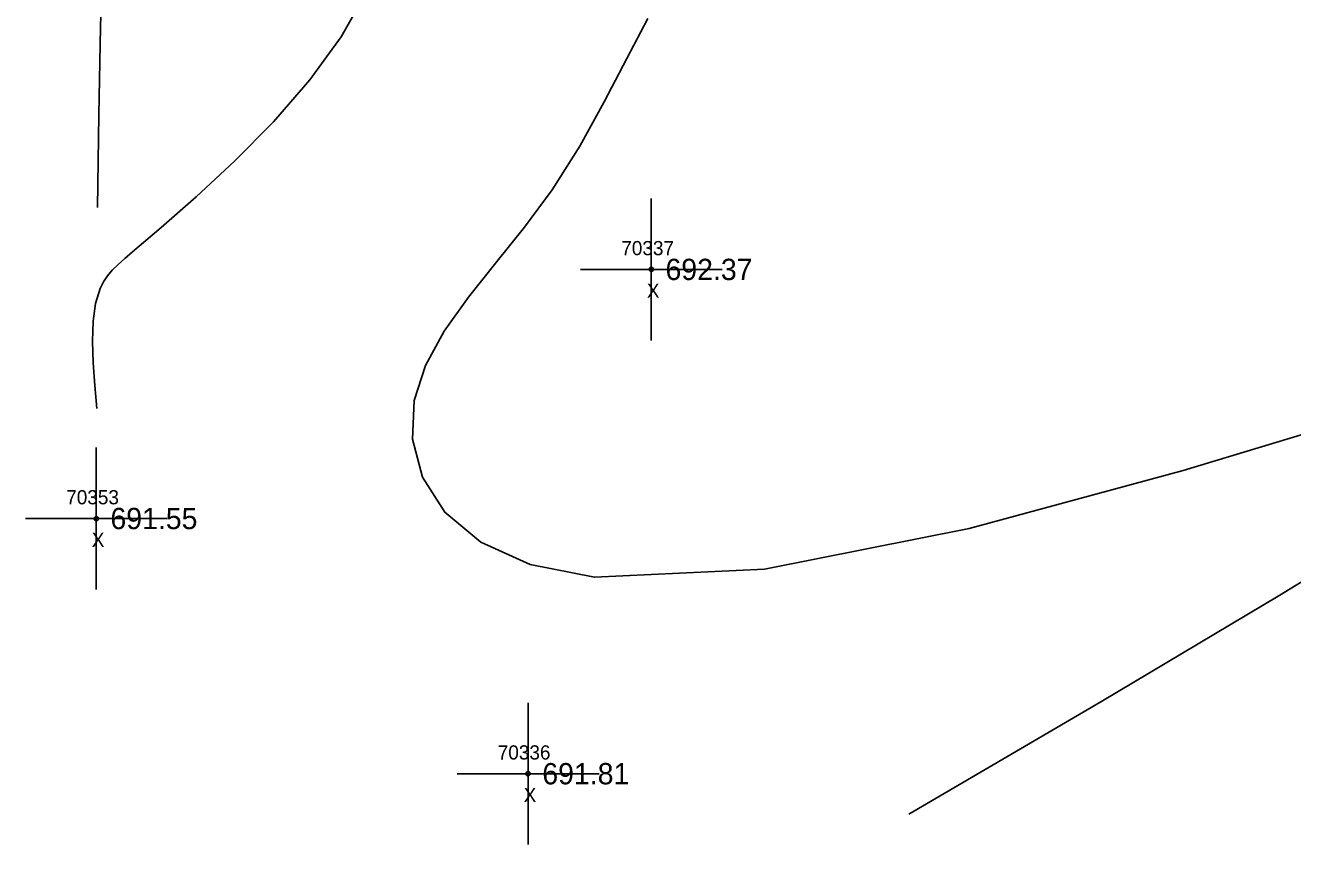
# Model space of a CAD drawing. Extents: x 1376587 to 1378239, y 1000335 to 1003031.
# Drawn here: x 1376920.8 to 1377010.1, y 1001454.8 to 1001512.6 of the extents above; entities that cross this region are included whole.
import ezdxf

# ---------------------------------------------------------------- set-up
doc = ezdxf.new("R2010")
doc.units = 0
for name, color, linetype in [('RD_DTM_Major1', 7, 'Continuous'), ('RD_DTM_Minor1', 7, 'Continuous'), ('RD_EX_Misc', 7, 'Continuous'), ('RD_EX_Misc_txCode', 7, 'Continuous'), ('RD_EX_TX_Misc_ELEV', 7, 'Continuous'), ('RD_SMD_Locator', 7, 'Continuous')]:
    doc.layers.add(name, color=color, linetype=linetype)

msp = doc.modelspace()

# ---------------------------------------------------------------- linework, layer by layer
at = {"layer": 'RD_DTM_Major1'}
msp.add_lwpolyline([(1376925.847, 1001499.751), (1376925.936, 1001506.285), (1376926.048, 1001512.49), (1376926.206, 1001518.039)], dxfattribs=at)
at = {"layer": 'RD_DTM_Minor1'}
for points in [[(1376925.785, 1001485.577), (1376925.643, 1001487.21), (1376925.532, 1001488.804), (1376925.483, 1001490.323), (1376925.527, 1001491.727), (1376925.695, 1001492.98), (1376926.018, 1001494.041), (1376926.252, 1001494.5), (1376926.539, 1001494.92), (1376926.883, 1001495.322), (1376927.29, 1001495.726), (1376927.765, 1001496.151), (1376928.311, 1001496.619), (1376930.322, 1001498.329), (1376932.786, 1001500.486), (1376935.496, 1001503.001), (1376938.243, 1001505.782), (1376940.817, 1001508.737), (1376943.012, 1001511.777), (1376944.196, 1001513.846)], [(1376964.634, 1001513.073), (1376963.151, 1001510.242), (1376961.572, 1001507.19), (1376959.843, 1001504.059), (1376957.908, 1001500.995), (1376955.953, 1001498.358), (1376953.931, 1001495.849), (1376951.991, 1001493.419), (1376950.283, 1001491.023), (1376948.957, 1001488.614), (1376948.161, 1001486.144), (1376948.044, 1001483.422), (1376948.753, 1001480.74), (1376950.341, 1001478.263), (1376952.858, 1001476.153), (1376956.355, 1001474.573), (1376960.882, 1001473.687), (1376972.858, 1001474.245), (1376987.309, 1001477.123), (1377002.386, 1001481.21), (1377016.237, 1001485.398)], [(1377020.057, 1001479.071), (1377009.215, 1001472.419), (1376996.579, 1001464.913), (1376983.046, 1001456.981)]]:
    msp.add_lwpolyline(points, dxfattribs=at)
at = {"layer": 'RD_EX_Misc'}
for p, q in [((1376964.889, 1001490.382), (1376964.889, 1001500.382)), ((1376959.889, 1001495.382), (1376969.889, 1001495.382)), ((1376925.751, 1001472.824), (1376925.751, 1001482.824)), ((1376920.751, 1001477.824), (1376930.751, 1001477.824)), ((1376956.202, 1001454.836), (1376956.202, 1001464.836)), ((1376951.202, 1001459.836), (1376961.202, 1001459.836))]:
    msp.add_line(p, q, dxfattribs=at)
at = {"layer": 'RD_SMD_Locator'}
for centre in [(1376964.889, 1001495.382), (1376925.751, 1001477.824), (1376956.202, 1001459.836)]:
    msp.add_circle(centre, 0.15, dxfattribs=at)

# ---------------------------------------------------------------- texts
at = {"layer": 'RD_EX_Misc_txCode'}
for s, p in [('70337', (1376962.771, 1001496.382)), ('X', (1376964.574, 1001493.382)), ('70353', (1376923.633, 1001478.824)), ('X', (1376925.436, 1001475.824)), ('70336', (1376954.06, 1001460.836)), ('X', (1376955.887, 1001457.836))]:
    msp.add_text(s, height=1, dxfattribs=at).set_placement(p)
at = {"layer": 'RD_EX_TX_Misc_ELEV'}
for s, p in [('692.37', (1376965.889, 1001494.632)), ('691.55', (1376926.751, 1001477.074)), ('691.81', (1376957.202, 1001459.086))]:
    msp.add_text(s, height=1.5, dxfattribs=at).set_placement(p)

doc.saveas('drawing.dxf')
